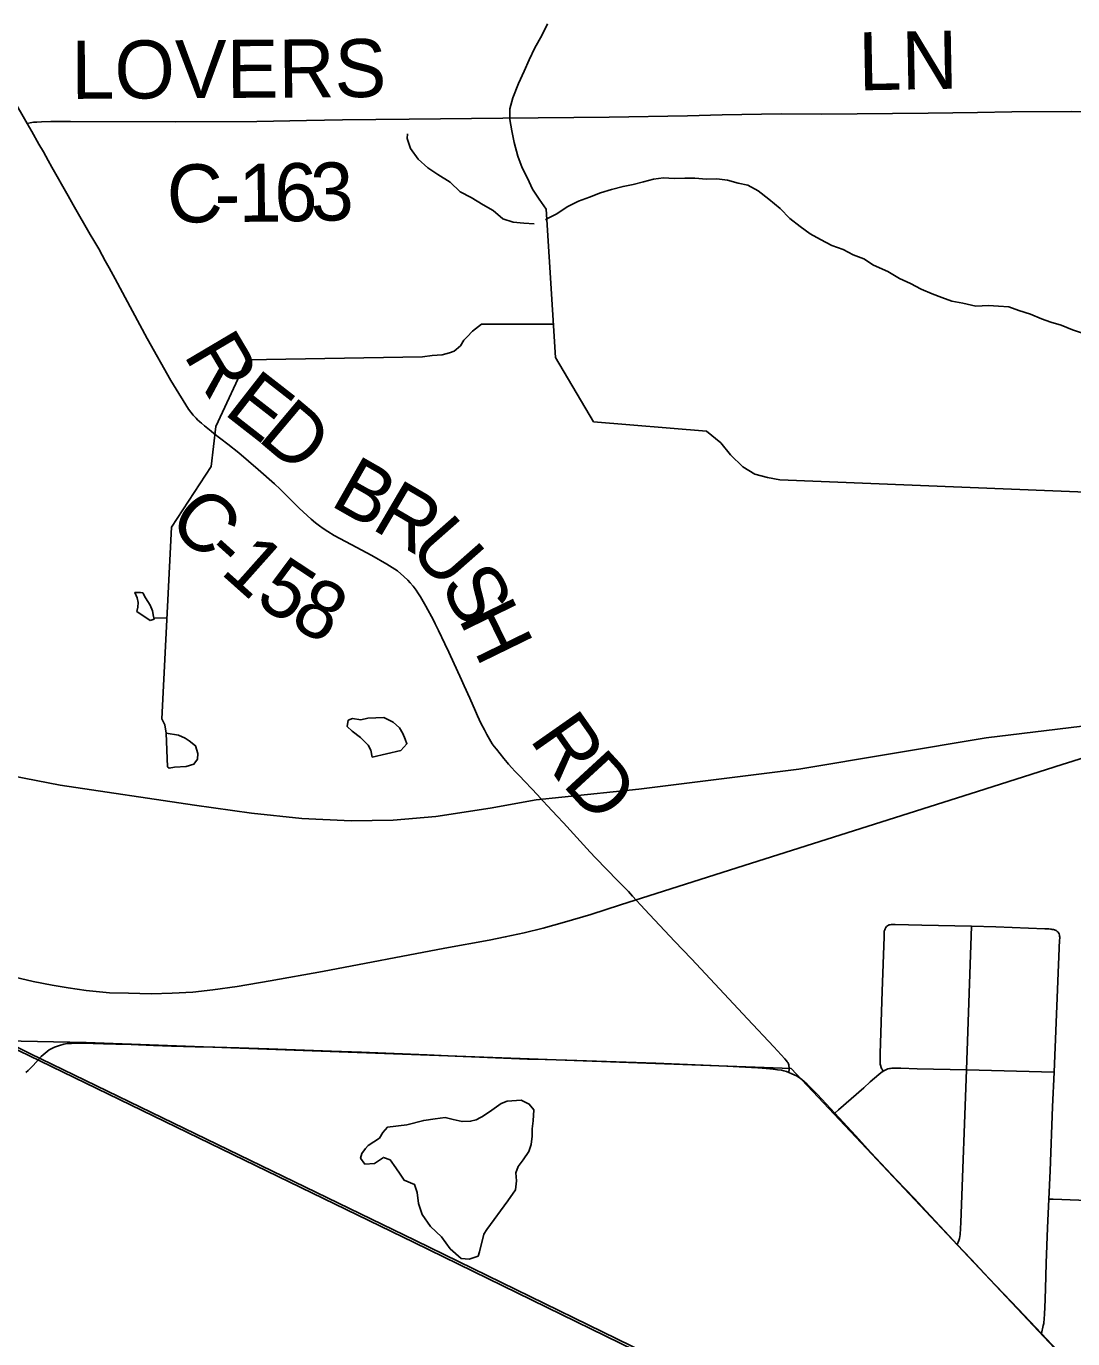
# Model space of a CAD drawing. Extents: x 0 to 34, y 0 to 22.
# Drawn here: x 5.303 to 6.327, y 14.669 to 15.953 of the extents above; entities that cross this region are included whole.
import ezdxf

# ---------------------------------------------------------------- set-up
doc = ezdxf.new("R2010")
doc.units = 0
for name, color, linetype in [('GM_X_County_Road', 7, 'Continuous'), ('GM_X_County_Road_Text', 7, 'Continuous'), ('GM_X_Minor_Lake', 7, 'Continuous'), ('GM_X_Minor_River', 7, 'Continuous'), ('GM_X_Rail_Line', 7, 'Continuous'), ('GM_X_Township_Road', 7, 'Continuous')]:
    doc.layers.add(name, color=color, linetype=linetype)

msp = doc.modelspace()

# ---------------------------------------------------------------- linework, layer by layer
at = {"layer": 'GM_X_County_Road'}
for points in [[(5.3042, 15.858), (5.2988, 15.8674), (5.2917, 15.8798), (5.2862, 15.8895), (5.28, 15.901), (5.2725, 15.9146), (5.2632, 15.9313), (5.247, 15.9603)], [(5.3042, 15.858), (5.307, 15.8587), (5.3104, 15.8593), (5.3137, 15.8596), (5.3183, 15.8599), (5.3272, 15.86), (5.3465, 15.8601), (5.449, 15.8599), (5.5289, 15.8602), (5.5775, 15.861), (5.6128, 15.8616), (5.6779, 15.8624), (5.7697, 15.8633), (5.8736, 15.8644), (5.9502, 15.8658), (5.9842, 15.8666), (6.0418, 15.8675), (6.0814, 15.8674), (6.1859, 15.8684), (6.2342, 15.869), (6.2676, 15.8695), (6.3265, 15.8698), (6.3588, 15.8696)], [(5.7814, 15.2245), (5.7783, 15.2278), (5.7753, 15.2312), (5.7739, 15.2328), (5.7705, 15.2369), (5.7633, 15.2458), (5.7612, 15.2486), (5.7593, 15.2512), (5.7564, 15.2557), (5.7538, 15.2604), (5.7515, 15.2649), (5.7482, 15.2713), (5.7447, 15.2787), (5.7427, 15.2832), (5.7373, 15.2957), (5.7317, 15.308), (5.7291, 15.3138), (5.7166, 15.3409), (5.7127, 15.3491), (5.7065, 15.3622), (5.7033, 15.3687), (5.7016, 15.372), (5.6942, 15.386), (5.689, 15.3951), (5.6865, 15.399), (5.6847, 15.4014), (5.6818, 15.4053), (5.6789, 15.4088), (5.6766, 15.4113), (5.6727, 15.415), (5.6665, 15.4203), (5.6614, 15.4238), (5.6561, 15.4271), (5.6415, 15.4354), (5.6211, 15.4461), (5.6047, 15.455), (5.5985, 15.4588), (5.5938, 15.4619), (5.5903, 15.4644), (5.5864, 15.4674), (5.5821, 15.471), (5.5702, 15.4819), (5.5517, 15.5002), (5.5462, 15.5054), (5.5303, 15.5197), (5.5112, 15.5358), (5.5005, 15.5444), (5.4869, 15.5548), (5.4841, 15.557), (5.4778, 15.5623), (5.4747, 15.5649), (5.4731, 15.5663), (5.4709, 15.5683), (5.4695, 15.5697), (5.4687, 15.5705), (5.4667, 15.5727), (5.4642, 15.5758), (5.4621, 15.5786), (5.4474, 15.6023), (5.4448, 15.6068), (5.4217, 15.6477), (5.4071, 15.6744), (5.3902, 15.7062), (5.3844, 15.7169), (5.3806, 15.7238), (5.3776, 15.7292), (5.3741, 15.7354), (5.3693, 15.7436), (5.3659, 15.7495), (5.3492, 15.7786), (5.3443, 15.7873), (5.3284, 15.8154), (5.3248, 15.8219), (5.32, 15.8304), (5.3157, 15.8379), (5.3086, 15.8503), (5.3042, 15.858)], [(5.8133, 15.1905), (5.8091, 15.1952), (5.8035, 15.2012), (5.7856, 15.2201), (5.7814, 15.2245)], [(6.0496, 14.9297), (6.0499, 14.9331), (6.0498, 14.9346), (6.0496, 14.9362), (6.0494, 14.9371), (6.0491, 14.938), (6.0488, 14.9387), (6.0484, 14.9394), (6.0479, 14.9401), (6.0471, 14.9411), (6.0456, 14.943), (6.0348, 14.9547), (6.0091, 14.9821), (5.9772, 15.0163), (5.9542, 15.0408), (5.9375, 15.0582), (5.9084, 15.089), (5.8966, 15.1022), (5.8925, 15.1066), (5.882, 15.1171), (5.8603, 15.1397), (5.8552, 15.1451), (5.8386, 15.1632), (5.8288, 15.1739), (5.8227, 15.1805), (5.8133, 15.1905)], [(5.3027, 14.9295), (5.3052, 14.9316), (5.31, 14.9363), (5.3179, 14.9451), (5.3216, 14.9486), (5.3258, 14.9516), (5.3308, 14.9542), (5.3356, 14.956), (5.3399, 14.9572), (5.3433, 14.9578), (5.3474, 14.9581), (5.3574, 14.9584), (5.3686, 14.958), (5.3787, 14.9577), (5.3909, 14.9572), (5.4058, 14.9568), (5.4276, 14.9559), (5.4455, 14.9554), (5.4685, 14.9547), (5.4878, 14.9543), (5.5111, 14.9537), (5.5405, 14.9528), (5.5668, 14.9519), (5.602, 14.9506), (5.6314, 14.9495), (5.6633, 14.948), (5.6956, 14.9468), (5.7229, 14.9457), (5.7546, 14.9444), (5.7937, 14.9427), (5.8111, 14.9422), (5.8322, 14.9417), (5.9192, 14.9386), (5.9887, 14.9356), (6.0192, 14.934), (6.0272, 14.9335), (6.0341, 14.9329), (6.0383, 14.9323), (6.0423, 14.9317), (6.0447, 14.9312), (6.0471, 14.9305), (6.0496, 14.9297)], [(6.0496, 14.9297), (6.0524, 14.9284), (6.0547, 14.9274), (6.057, 14.9262), (6.0595, 14.9246), (6.0622, 14.9227), (6.0675, 14.9182), (6.0776, 14.908), (6.0944, 14.8898)], [(6.0944, 14.8898), (6.1147, 14.8678), (6.1297, 14.8512), (6.1549, 14.8247), (6.172, 14.8066), (6.1838, 14.7939), (6.2063, 14.7698), (6.2143, 14.7613)], [(6.2143, 14.7613), (6.2279, 14.747), (6.2453, 14.7283), (6.2739, 14.6983), (6.2968, 14.6742)], [(6.2968, 14.6742), (6.322, 14.647), (6.348, 14.619), (6.3644, 14.602), (6.3793, 14.5865)]]:
    msp.add_lwpolyline(points, dxfattribs=at)
at = {"layer": 'GM_X_Minor_Lake'}
for p, q in [((5.4116, 15.3807), (5.4246, 15.3717)), ((5.4402, 15.2615), (5.4416, 15.2285)), ((5.6417, 15.238), (5.6697, 15.2447)), ((5.7539, 14.7759), (5.7745, 14.8041))]:
    msp.add_line(p, q, dxfattribs=at)
for points in [[(5.4246, 15.3717), (5.4283, 15.3733), (5.4279, 15.3759), (5.4268, 15.3812), (5.4244, 15.3869), (5.4198, 15.3941), (5.4172, 15.399), (5.4149, 15.3993), (5.4096, 15.3993), (5.4119, 15.394), (5.4127, 15.3895), (5.4123, 15.3849), (5.4116, 15.3807)], [(5.6697, 15.2447), (5.6757, 15.2512), (5.6741, 15.2557), (5.6718, 15.2614), (5.6684, 15.2667), (5.6623, 15.2723), (5.6532, 15.2768), (5.6376, 15.2763), (5.6308, 15.2747), (5.6225, 15.2758), (5.6184, 15.2743), (5.6173, 15.2682), (5.6222, 15.2637), (5.6302, 15.2573), (5.6378, 15.2498), (5.6405, 15.2449), (5.6417, 15.238)], [(5.4416, 15.2285), (5.4431, 15.2274), (5.4484, 15.2282), (5.4597, 15.229), (5.4673, 15.2314), (5.4707, 15.236), (5.471, 15.2416), (5.4687, 15.2492), (5.4626, 15.2541), (5.4588, 15.2567), (5.4523, 15.2597), (5.4402, 15.2615)], [(5.7745, 14.8041), (5.782, 14.8148), (5.7831, 14.8235), (5.7823, 14.8314), (5.7845, 14.8375), (5.7894, 14.844), (5.795, 14.8524), (5.7972, 14.8592), (5.7983, 14.8672), (5.7982, 14.8744), (5.7993, 14.8824), (5.8, 14.893), (5.7954, 14.8987), (5.7874, 14.9024), (5.7738, 14.9015), (5.7681, 14.8992), (5.7587, 14.8927), (5.7497, 14.8866), (5.7478, 14.8854), (5.7436, 14.8831), (5.738, 14.8819), (5.7297, 14.8815), (5.7209, 14.8837), (5.7133, 14.8855), (5.7035, 14.8843), (5.6922, 14.8827), (5.6756, 14.8784), (5.6566, 14.876), (5.6521, 14.871), (5.6488, 14.8653), (5.6379, 14.858), (5.6352, 14.8553), (5.6315, 14.8504), (5.6304, 14.8458), (5.6346, 14.8398), (5.6441, 14.8406), (5.6527, 14.8464), (5.6592, 14.8441), (5.6649, 14.8362), (5.6691, 14.8302), (5.6729, 14.8242), (5.6832, 14.8201), (5.6859, 14.8121), (5.6871, 14.8015), (5.6906, 14.7905), (5.6987, 14.7788), (5.7097, 14.7687), (5.7181, 14.757), (5.7288, 14.7476), (5.7368, 14.7469), (5.7454, 14.75), (5.7469, 14.7542), (5.7509, 14.7713), (5.7539, 14.7759)]]:
    msp.add_lwpolyline(points, dxfattribs=at)
at = {"layer": 'GM_X_Minor_River'}
for p, q in [((5.812, 15.7744), (5.8211, 15.6293)), ((5.8211, 15.6293), (5.8583, 15.5662)), ((5.8583, 15.5662), (5.9689, 15.5572)), ((5.9689, 15.5572), (5.983, 15.5456)), ((5.983, 15.5456), (5.9925, 15.5339)), ((5.9925, 15.5339), (6.0044, 15.5222)), ((6.0044, 15.5222), (6.0162, 15.5151)), ((6.0162, 15.5151), (6.0287, 15.5118)), ((6.0287, 15.5118), (6.0408, 15.5096)), ((6.0408, 15.5096), (6.4115, 15.4946))]:
    msp.add_line(p, q, dxfattribs=at)
for points in [[(5.7986, 15.794), (5.7936, 15.8046), (5.7886, 15.8148), (5.7843, 15.8262), (5.7808, 15.8394), (5.7785, 15.8508), (5.7765, 15.8621), (5.7764, 15.8724), (5.7794, 15.8834), (5.7849, 15.8974), (5.7905, 15.9092), (5.7953, 15.9203), (5.8009, 15.9321), (5.8076, 15.9443), (5.8132, 15.9557)], [(5.8004, 15.7599), (5.7902, 15.7606), (5.7796, 15.7617), (5.7697, 15.765), (5.7602, 15.7729), (5.7503, 15.7785), (5.7385, 15.7856), (5.7279, 15.7912), (5.7179, 15.8006), (5.7061, 15.8081), (5.6963, 15.8149), (5.6867, 15.8231), (5.6791, 15.8337), (5.676, 15.8435), (5.6763, 15.8481)], [(6.3379, 15.6526), (6.3269, 15.6563), (6.3159, 15.6608), (6.306, 15.6637), (6.2966, 15.6671), (6.2859, 15.6715), (6.2745, 15.6752), (6.2647, 15.6789), (6.2548, 15.6793), (6.245, 15.6799), (6.2325, 15.6795), (6.2196, 15.6824), (6.209, 15.6842), (6.1991, 15.6879), (6.1896, 15.6916), (6.179, 15.6961), (6.1684, 15.7017), (6.1577, 15.7066), (6.1463, 15.7133), (6.1323, 15.7196), (6.1228, 15.7256), (6.1125, 15.7297), (6.1026, 15.735), (6.0916, 15.7387), (6.0806, 15.7446), (6.0703, 15.7503), (6.0604, 15.7574), (6.0505, 15.7653), (6.041, 15.7751), (6.0299, 15.7841), (6.0193, 15.7923), (6.0094, 15.7979), (5.9999, 15.7998), (5.9893, 15.8027), (5.9791, 15.8041), (5.9689, 15.8037), (5.9575, 15.8047), (5.9476, 15.8047), (5.9374, 15.8042), (5.9268, 15.8049), (5.917, 15.8037), (5.9072, 15.8009), (5.897, 15.7986), (5.8872, 15.7966), (5.8758, 15.7935), (5.8652, 15.7904), (5.8543, 15.7861), (5.8437, 15.7822), (5.8324, 15.7765), (5.8223, 15.7699), (5.8125, 15.7649), (5.8113, 15.7638)], [(5.812, 15.7744), (5.8051, 15.7842), (5.7986, 15.794)], [(5.8191, 15.6619), (5.7486, 15.6617), (5.7399, 15.6548), (5.7346, 15.6494), (5.7313, 15.646), (5.7283, 15.6407), (5.7219, 15.6353), (5.7174, 15.6338), (5.7102, 15.6318), (5.7003, 15.631), (5.6909, 15.6298), (5.5191, 15.6269), (5.4886, 15.5618), (5.4843, 15.5224), (5.4454, 15.4633), (5.4359, 15.2755), (5.4389, 15.2697), (5.4402, 15.2615)], [(5.4409, 15.3741), (5.4282, 15.3744)]]:
    msp.add_lwpolyline(points, dxfattribs=at)
at = {"layer": 'GM_X_Rail_Line'}
for points in [[(6.8117, 14.2126), (6.7279, 14.2533), (6.3597, 14.4329), (6.2736, 14.4747), (5.6829, 14.7631), (5.3058, 14.9462), (5.2814, 14.958), (4.9779, 15.1046), (4.4205, 15.3745)], [(6.8127, 14.2147), (6.7289, 14.2554), (6.3608, 14.435), (6.2746, 14.4768), (5.684, 14.7652), (5.3068, 14.9483), (5.2824, 14.9601), (4.9789, 15.1067), (4.4214, 15.3767)], [(4.537, 15.3672), (4.5736, 15.3621), (4.6157, 15.3522), (5.0206, 15.272), (5.3364, 15.2108), (5.4679, 15.1911), (5.5237, 15.1833), (5.573, 15.1781), (5.6211, 15.1758), (5.6624, 15.1766), (5.704, 15.1802), (5.7573, 15.1883), (5.8023, 15.1965), (5.9026, 15.2069), (6.0592, 15.2263), (6.2427, 15.2569), (6.4412, 15.2812)], [(5.2921, 15.0227), (5.31, 15.0185), (5.3286, 15.0149), (5.3442, 15.0124), (5.362, 15.0099), (5.3847, 15.0075), (5.4033, 15.0071), (5.4256, 15.0067), (5.446, 15.0071), (5.4661, 15.0082), (5.4858, 15.0104), (5.5095, 15.0138), (5.5418, 15.0194), (5.593, 15.0285), (5.713, 15.0512), (5.7561, 15.0592), (5.7719, 15.0623), (5.7904, 15.0661), (5.8091, 15.0707), (5.8299, 15.0765), (5.8557, 15.0843), (5.8846, 15.0937), (5.9197, 15.1048), (6.0056, 15.132), (6.2341, 15.2046), (6.317, 15.231), (6.3658, 15.2462)], [(7.7906, 14.1), (7.7891, 14.1611), (7.792, 14.368), (7.7915, 14.4601), (7.677, 14.4615), (7.605, 14.4663), (7.4966, 14.4734), (7.0511, 14.4887), (6.6677, 14.502), (6.4516, 14.5087), (6.0517, 14.9336), (5.3617, 14.959), (5.2822, 14.9606)]]:
    msp.add_lwpolyline(points, dxfattribs=at)
at = {"layer": 'GM_X_Township_Road'}
for q in [(6.2283, 15.0727), (6.309, 14.9298)]:
    msp.add_line((6.2232, 14.9322), q, dxfattribs=at)
for points in [[(6.1417, 14.9308), (6.1411, 14.9319), (6.1407, 14.9327), (6.1403, 14.9335), (6.1395, 14.9353), (6.1394, 14.9359), (6.1392, 14.9367), (6.139, 14.9377), (6.1389, 14.9394), (6.1388, 14.943), (6.1388, 14.948), (6.1408, 15.0091), (6.1426, 15.0622), (6.1426, 15.0648), (6.1427, 15.0665), (6.1429, 15.068), (6.1433, 15.0691), (6.1437, 15.0702), (6.1445, 15.0715), (6.1452, 15.0724), (6.1461, 15.0731)], [(6.1461, 15.0731), (6.147, 15.0736), (6.1478, 15.074), (6.1486, 15.0742), (6.1498, 15.0744), (6.1511, 15.0744), (6.152, 15.0744), (6.1536, 15.0744), (6.1795, 15.0738), (6.2283, 15.0727)], [(6.2283, 15.0727), (6.252, 15.072), (6.3001, 15.0702), (6.3023, 15.0701), (6.304, 15.07), (6.3054, 15.0698), (6.3061, 15.0697), (6.3072, 15.0696), (6.3083, 15.0694), (6.3093, 15.0691), (6.3102, 15.0689), (6.3111, 15.0684), (6.3122, 15.0676), (6.3129, 15.067)], [(6.309, 14.9298), (6.3144, 15.0593), (6.3145, 15.0608), (6.3145, 15.0619), (6.3144, 15.063), (6.3142, 15.064), (6.3139, 15.0652), (6.3134, 15.0662), (6.3129, 15.067)], [(6.0944, 14.8898), (6.0981, 14.893), (6.1227, 14.9147), (6.1292, 14.9203), (6.1376, 14.9276), (6.1395, 14.9292), (6.1417, 14.9308)], [(6.1417, 14.9308), (6.1431, 14.9316), (6.1445, 14.9323), (6.1458, 14.9329), (6.1465, 14.9331), (6.148, 14.9334), (6.1489, 14.9335), (6.1504, 14.9337), (6.1517, 14.9338), (6.1536, 14.9338), (6.159, 14.9338), (6.1749, 14.9333), (6.2232, 14.9322)], [(6.2143, 14.7613), (6.2158, 14.7652), (6.2164, 14.7672), (6.2168, 14.7691), (6.217, 14.7712), (6.2174, 14.7769), (6.2178, 14.7829), (6.2232, 14.9322)], [(6.304, 14.8056), (6.3053, 14.8334), (6.3076, 14.896), (6.309, 14.9298)], [(6.2968, 14.6742), (6.2985, 14.682), (6.2989, 14.684), (6.2991, 14.6855), (6.2993, 14.6874), (6.2998, 14.6941), (6.3, 14.699), (6.3005, 14.7178), (6.3014, 14.7429), (6.3026, 14.7776), (6.304, 14.8056)], [(6.304, 14.8056), (6.3081, 14.8055), (6.3915, 14.8024)]]:
    msp.add_lwpolyline(points, dxfattribs=at)

# ---------------------------------------------------------------- texts
at = {"layer": 'GM_X_County_Road_Text'}
for s, height, rotation, p in [('LOVERS', 0.05682, 0.3519, (5.3475, 15.8822)), ('LN', 0.05682, 1.0317, (6.118, 15.8905)), ('C', 0.0568, 0.5816, (5.441, 15.7611)), ('1', 0.0568, 0.6491, (5.5111, 15.7618)), ('6', 0.0568, 0.833, (5.5463, 15.7622)), ('3', 0.0568, 1.3824, (5.5819, 15.7627)), ('-', 0.0568, 0.5858, (5.4877, 15.7616)), ('R', 0.0568, 300.6231, (5.4565, 15.632)), ('E', 0.0568, 322.0428, (5.4952, 15.5748)), ('D', 0.0568, 319.8717, (5.5283, 15.549)), ('B', 0.0568, 330.3824, (5.5993, 15.4852)), ('R', 0.0568, 329.5885, (5.6397, 15.4622)), ('C', 0.0568, 317.982, (5.4398, 15.4656)), ('U', 0.0568, 311.3682, (5.6763, 15.4416)), ('-', 0.0568, 318.0314, (5.4745, 15.4344)), ('1', 0.0568, 318.3042, (5.4921, 15.4186)), ('5', 0.0568, 326.6636, (5.5254, 15.3898)), ('S', 0.0568, 299.0648, (5.7075, 15.4067)), ('8', 0.0568, 331.7215, (5.5593, 15.3677)), ('H', 0.0568, 295.9916, (5.7257, 15.3739)), ('R', 0.0568, 304.9891, (5.795, 15.2557)), ('D', 0.0568, 312.6175, (5.8268, 15.2111))]:
    msp.add_text(s, height=height, rotation=rotation, dxfattribs=at).set_placement(p)

doc.saveas('drawing.dxf')
